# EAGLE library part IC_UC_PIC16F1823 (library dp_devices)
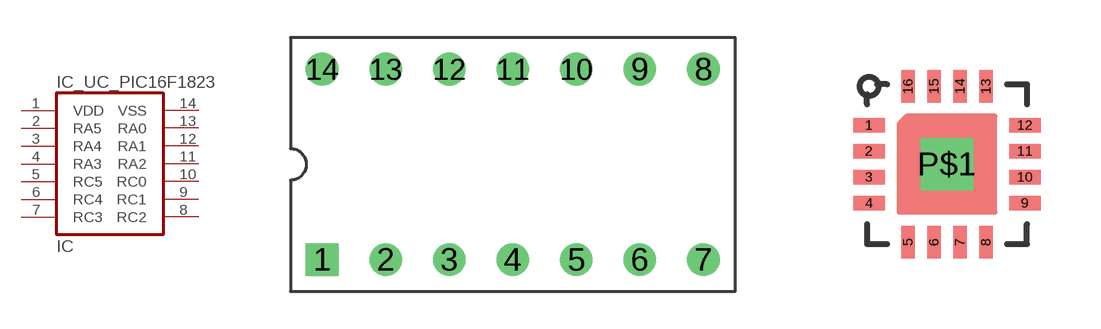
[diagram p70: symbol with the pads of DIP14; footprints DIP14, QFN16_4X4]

Designator prefix IC

## IC_UC_PIC16F1823-DIL14, IC_UC_PIC16F1823PTH-DIL14  [DIP14]
1  VDD  pwr
2  RA5
3  RA4
4  RA3
5  RC5
6  RC4
7  RC3
8  RC2
9  RC1
10  RC0
11  RA2
12  RA1
13  RA0
14  VSS  pwr

## IC_UC_PIC16F1823-QFN16_4X4  [QFN16_4X4]
1  RA5
2  RA4
3  RA3
4  RC5
5  RC4
6  RC3
7  RC2
8  RC1
9  RC0
10  RA2
11  RA1
12  RA0
13  VSS  pwr
16  VDD  pwr

## IC_UC_PIC16F1823-SOIC14  [SOIC-14]
Pads as for DIP14

## Footprint DIP14 (pad centres in mm)
drill 0.8 square: 1 -7.62,-3.81
drill 0.8 round: 2 -5.08,-3.81; 3 -2.54,-3.81; 4 0,-3.81; 5 2.54,-3.81; 6 5.08,-3.81; 7 7.62,-3.81; 8 7.62,3.81; 9 5.08,3.81; 10 2.54,3.81; 11 0,3.81; 12 -2.54,3.81; 13 -5.08,3.81; 14 -7.62,3.81

## Footprint QFN16_4X4 (pad centres in mm)
smd 0.8 x 0.35: 1 -1.95,0.975; 2 -1.95,0.325; 3 -1.95,-0.325; 4 -1.95,-0.975; 9 1.95,-0.975; 10 1.95,-0.325; 11 1.95,0.325; 12 1.95,0.975
smd 0.35 x 0.8: 5 -0.975,-1.95; 6 -0.325,-1.95; 7 0.325,-1.95; 8 0.975,-1.95; 13 0.975,1.95; 14 0.325,1.95; 15 -0.325,1.95; 16 -0.975,1.95
drill 0.8 square: P$1 0,0

## Footprint SOIC-14 (pad centres in mm)
SSOP-14, 0.6 x 1.5 mm pad, 1.27mm pad pitch
smd 0.6 x 1.5: 1 -3.81,-2.7; 2 -2.54,-2.7; 3 -1.27,-2.7; 4 0,-2.7; 5 1.27,-2.7; 6 2.54,-2.7; 7 3.81,-2.7; 8 3.81,2.7; 9 2.54,2.7; 10 1.27,2.7; 11 0,2.7; 12 -1.27,2.7; 13 -2.54,2.7; 14 -3.81,2.7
